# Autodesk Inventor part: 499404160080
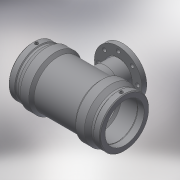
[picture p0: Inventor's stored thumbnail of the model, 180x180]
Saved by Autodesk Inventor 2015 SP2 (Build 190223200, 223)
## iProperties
Created: 2017-06
Part Number: 499404160080
Material: Generic
Description: PLASSON FLANGED TEE 160x80x160
Document SubType Name: Modeling
Designer: KIM
Mass: 57.3761 g
Surface Area: 241.06 cm^2
Volume: 57.3761 cm^3
Density: 1 g/cm^3
Appearance: Default
Author: KIM
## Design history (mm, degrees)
derived "499404.ipt"
feature "Solid1::499404.ipt"
tag "TaggingFeature1"
body "Solid1"
other parameters: "d14" = 17.6296, "d17" = 144, "d19" = 3.52592, "d20" = 168 deg, "d22" = 193.44, "d23" = 208, "d24" = 187.6368, "d25" = 135 deg, "d26" = 308, "d27" = 135 deg, "d29" = 106, "d35" = 15, "d39" = 5 deg, "d45" = 4, "d46" = 14, "d47" = 0, "d55" = 187.2, "d56" = 208, "d57" = 154, "d58" = 135 deg, "d59" = 86, "d60" = 86, "d61" = 135 deg, "d72" = 200.2, "d73" = 100.1, "d87" = 138, "d89" = 96, "d91" = 15 deg, "d92" = 104, "d95" = 4.14, "d97" = 18, "d100" = 0, "d102" = 360 deg, "d105" = 0, "d107" = 0, "d108" = 3, "d109" = 0, "d110" = 25.8, "d111" = 8.6, "L_1" = 86, "D_" = 208, "A_" = 106, "d_2" = 12, "d_1" = 138, "s_" = 18
